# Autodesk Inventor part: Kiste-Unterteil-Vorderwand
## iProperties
Manager: Dr.-Ing. Roland Schröder
Company: www.Das-Entwicklungsbuero.de
Created: 2006-09
Part Number: Kiste-Unterteil-Vorderwand
Project: 12107
Document SubType Name: Modeling
Designer: rsc
Engineer: Dr.-Ing. Roland Schröder
Oberflächen: Ra 6,4
Toleranzen: ISO 2768 - m
Kanten: brechen
Author: rsc
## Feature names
1. Extrusion1
2. Trennen1
